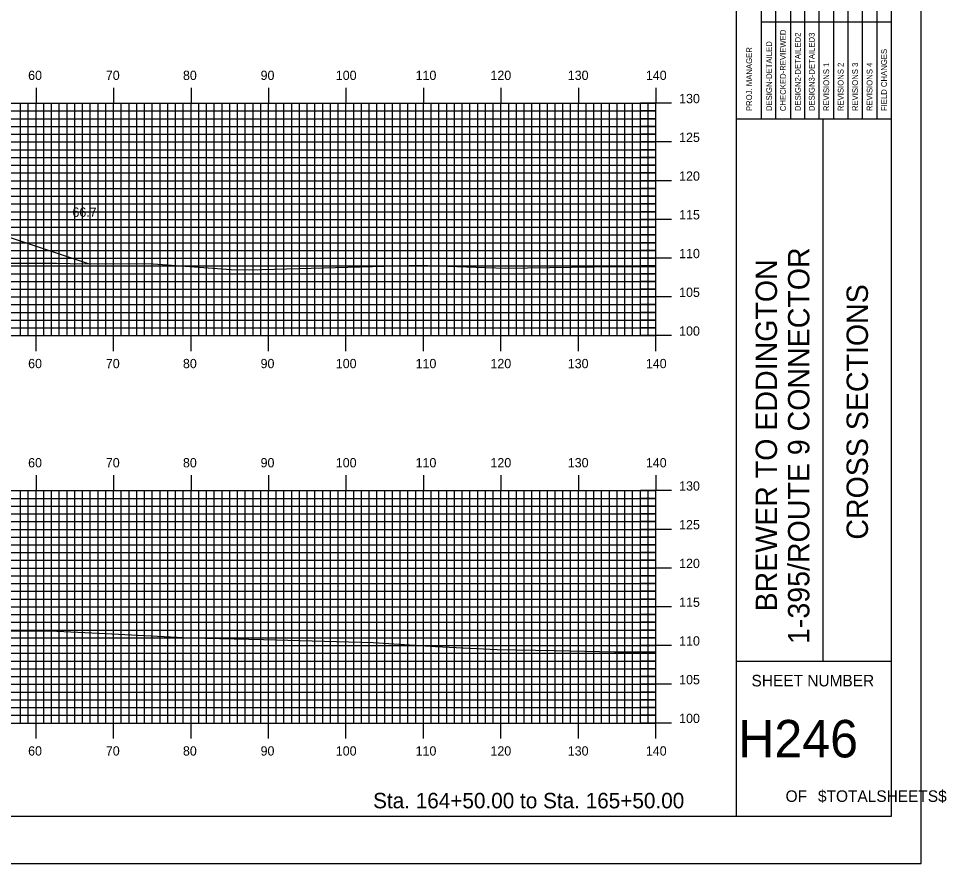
# Model space of a CAD drawing. Extents: x 1781073 to 1781416, y 442591 to 442811.
# Drawn here: x 1781296.6 to 1781416.4, y 442590.5 to 442699.6 of the extents above; entities that cross this region are included whole.
import ezdxf

# ---------------------------------------------------------------- set-up
doc = ezdxf.new("R2010")
doc.units = 0
for name, color, linetype in [('BORDER', 7, 'Continuous'), ('D_Roadway_Centerline', 7, 'Continuous'), ('D_Roadway_SlopeLines', 7, 'Continuous'), ('D_Text_Standard', 7, 'Continuous'), ('H_V ANNOTATION', 7, 'Continuous'), ('MAJOR', 7, 'Continuous'), ('MINOR', 7, 'Continuous'), ('PLOT BOUNDARY', 7, 'Continuous'), ('S_Roadway_Centerline', 7, 'Continuous')]:
    doc.layers.add(name, color=color, linetype=linetype)

msp = doc.modelspace()

# ---------------------------------------------------------------- linework, layer by layer
at = {"layer": 'BORDER'}
for p, q in [((1781389.29, 442596.67), (1781389.29, 442806.67)), ((1781389.29, 442686.67), (1781409.29, 442686.67)), ((1781400.48, 442616.67), (1781400.48, 442686.67)), ((1781389.29, 442616.67), (1781409.29, 442616.67))]:
    msp.add_line(p, q, dxfattribs=at)
msp.add_lwpolyline([(1781089.29, 442596.67), (1781409.29, 442596.67), (1781409.29, 442806.67), (1781089.29, 442806.67)], close=True, dxfattribs=at)
for points in [[(1781394.39, 442686.68), (1781394.39, 442721.67)], [(1781396.25, 442721.67), (1781396.25, 442686.68)], [(1781398.12, 442686.68), (1781398.12, 442721.67)], [(1781399.98, 442686.68), (1781399.98, 442721.67)], [(1781401.84, 442686.68), (1781401.84, 442721.67)], [(1781403.71, 442686.68), (1781403.71, 442721.67)], [(1781405.57, 442686.68), (1781405.57, 442721.67)], [(1781407.43, 442686.68), (1781407.43, 442721.67)], [(1781392.53, 442686.68), (1781392.53, 442720.26)], [(1781392.52, 442699.17), (1781409.29, 442699.17)]]:
    msp.add_lwpolyline(points, dxfattribs=at)
at = {"layer": 'D_Roadway_Centerline'}
msp.add_lwpolyline([(1781185.99, 442672.58), (1781206.89, 442679.55), (1781208.72, 442680.01), (1781218.89, 442682.55), (1781226.89, 442682.87), (1781238.89, 442683.11), (1781250.89, 442682.87), (1781258.89, 442682.55), (1781269.07, 442680.01), (1781270.89, 442679.55), (1781305.63, 442667.98)], dxfattribs=at)
at = {"layer": 'D_Roadway_SlopeLines'}
msp.add_lwpolyline([(1781258.89, 442682.55), (1781270.89, 442679.55), (1781305.63, 442667.98)], dxfattribs=at)
at = {"layer": 'MAJOR'}
for p, q in [((1781298.89, 442690.67), (1781298.89, 442688.67)), ((1781308.89, 442690.67), (1781308.89, 442688.67)), ((1781318.89, 442690.67), (1781318.89, 442688.67)), ((1781328.89, 442690.67), (1781328.89, 442688.67)), ((1781338.89, 442690.67), (1781338.89, 442688.67)), ((1781348.89, 442690.67), (1781348.89, 442688.67)), ((1781358.89, 442690.67), (1781358.89, 442688.67)), ((1781368.89, 442690.67), (1781368.89, 442688.67)), ((1781378.89, 442690.67), (1781378.89, 442688.67)), ((1781098.89, 442688.67), (1781378.89, 442688.67)), ((1781098.89, 442688.67), (1781378.89, 442688.67)), ((1781298.89, 442658.67), (1781298.89, 442688.67)), ((1781308.89, 442658.67), (1781308.89, 442688.67)), ((1781318.89, 442658.67), (1781318.89, 442688.67)), ((1781328.89, 442658.67), (1781328.89, 442688.67)), ((1781338.89, 442658.67), (1781338.89, 442688.67)), ((1781348.89, 442658.67), (1781348.89, 442688.67)), ((1781358.89, 442658.67), (1781358.89, 442688.67)), ((1781368.89, 442658.67), (1781368.89, 442688.67)), ((1781380.9, 442688.67), (1781376.89, 442688.67)), ((1781378.89, 442658.67), (1781378.89, 442688.67)), ((1781378.89, 442658.67), (1781378.89, 442688.67)), ((1781098.89, 442683.67), (1781378.89, 442683.67)), ((1781380.9, 442683.67), (1781376.89, 442683.67)), ((1781098.89, 442678.67), (1781378.89, 442678.67)), ((1781380.9, 442678.67), (1781376.89, 442678.67)), ((1781098.89, 442673.67), (1781378.89, 442673.67)), ((1781380.9, 442673.67), (1781376.89, 442673.67)), ((1781098.89, 442668.67), (1781378.89, 442668.67)), ((1781380.9, 442668.67), (1781376.89, 442668.67)), ((1781098.89, 442663.67), (1781378.89, 442663.67)), ((1781380.9, 442663.67), (1781376.89, 442663.67)), ((1781098.89, 442658.67), (1781378.89, 442658.67)), ((1781098.89, 442658.67), (1781378.89, 442658.67)), ((1781298.89, 442656.66), (1781298.89, 442658.67)), ((1781308.89, 442656.66), (1781308.89, 442658.67)), ((1781318.89, 442656.66), (1781318.89, 442658.67)), ((1781328.89, 442656.66), (1781328.89, 442658.67)), ((1781338.89, 442656.66), (1781338.89, 442658.67)), ((1781348.89, 442656.66), (1781348.89, 442658.67)), ((1781358.89, 442656.66), (1781358.89, 442658.67)), ((1781368.89, 442656.66), (1781368.89, 442658.67)), ((1781380.9, 442658.67), (1781376.89, 442658.67)), ((1781378.89, 442656.66), (1781378.89, 442658.67)), ((1781298.89, 442640.67), (1781298.89, 442638.67)), ((1781308.89, 442640.67), (1781308.89, 442638.67)), ((1781318.89, 442640.67), (1781318.89, 442638.67)), ((1781328.89, 442640.67), (1781328.89, 442638.67)), ((1781338.89, 442640.67), (1781338.89, 442638.67)), ((1781348.89, 442640.67), (1781348.89, 442638.67)), ((1781358.89, 442640.67), (1781358.89, 442638.67)), ((1781368.89, 442640.67), (1781368.89, 442638.67)), ((1781378.89, 442640.67), (1781378.89, 442638.67)), ((1781098.89, 442638.67), (1781378.89, 442638.67)), ((1781098.89, 442638.67), (1781378.89, 442638.67)), ((1781298.89, 442608.67), (1781298.89, 442638.67)), ((1781308.89, 442608.67), (1781308.89, 442638.67)), ((1781318.89, 442608.67), (1781318.89, 442638.67)), ((1781328.89, 442608.67), (1781328.89, 442638.67)), ((1781338.89, 442608.67), (1781338.89, 442638.67)), ((1781348.89, 442608.67), (1781348.89, 442638.67)), ((1781358.89, 442608.67), (1781358.89, 442638.67)), ((1781368.89, 442608.67), (1781368.89, 442638.67)), ((1781380.9, 442638.67), (1781376.89, 442638.67)), ((1781378.89, 442608.67), (1781378.89, 442638.67)), ((1781378.89, 442608.67), (1781378.89, 442638.67)), ((1781098.89, 442633.67), (1781378.89, 442633.67)), ((1781380.9, 442633.67), (1781376.89, 442633.67)), ((1781098.89, 442628.67), (1781378.89, 442628.67)), ((1781380.9, 442628.67), (1781376.89, 442628.67)), ((1781098.89, 442623.67), (1781378.89, 442623.67)), ((1781380.9, 442623.67), (1781376.89, 442623.67)), ((1781098.89, 442618.67), (1781378.89, 442618.67)), ((1781380.9, 442618.67), (1781376.89, 442618.67)), ((1781098.89, 442613.67), (1781378.89, 442613.67)), ((1781380.9, 442613.67), (1781376.89, 442613.67)), ((1781098.89, 442608.67), (1781378.89, 442608.67)), ((1781098.89, 442608.67), (1781378.89, 442608.67)), ((1781298.89, 442606.66), (1781298.89, 442608.67)), ((1781308.89, 442606.66), (1781308.89, 442608.67)), ((1781318.89, 442606.66), (1781318.89, 442608.67)), ((1781328.89, 442606.66), (1781328.89, 442608.67)), ((1781338.89, 442606.66), (1781338.89, 442608.67)), ((1781348.89, 442606.66), (1781348.89, 442608.67)), ((1781358.89, 442606.66), (1781358.89, 442608.67)), ((1781368.89, 442606.66), (1781368.89, 442608.67)), ((1781380.9, 442608.67), (1781376.89, 442608.67)), ((1781378.89, 442606.66), (1781378.89, 442608.67))]:
    msp.add_line(p, q, dxfattribs=at)
at = {"layer": 'MINOR'}
for p, q in [((1781296.89, 442658.67), (1781296.89, 442688.67)), ((1781297.89, 442658.67), (1781297.89, 442688.67)), ((1781299.89, 442658.67), (1781299.89, 442688.67)), ((1781300.89, 442658.67), (1781300.89, 442688.67)), ((1781301.89, 442658.67), (1781301.89, 442688.67)), ((1781302.89, 442658.67), (1781302.89, 442688.67)), ((1781303.89, 442658.67), (1781303.89, 442688.67)), ((1781304.89, 442658.67), (1781304.89, 442688.67)), ((1781305.89, 442658.67), (1781305.89, 442688.67)), ((1781306.89, 442658.67), (1781306.89, 442688.67)), ((1781307.89, 442658.67), (1781307.89, 442688.67)), ((1781309.89, 442658.67), (1781309.89, 442688.67)), ((1781310.89, 442658.67), (1781310.89, 442688.67)), ((1781311.89, 442658.67), (1781311.89, 442688.67)), ((1781312.89, 442658.67), (1781312.89, 442688.67)), ((1781313.89, 442658.67), (1781313.89, 442688.67)), ((1781314.89, 442658.67), (1781314.89, 442688.67)), ((1781315.89, 442658.67), (1781315.89, 442688.67)), ((1781316.89, 442658.67), (1781316.89, 442688.67)), ((1781317.89, 442658.67), (1781317.89, 442688.67)), ((1781319.89, 442658.67), (1781319.89, 442688.67)), ((1781320.89, 442658.67), (1781320.89, 442688.67)), ((1781321.89, 442658.67), (1781321.89, 442688.67)), ((1781322.89, 442658.67), (1781322.89, 442688.67)), ((1781323.89, 442658.67), (1781323.89, 442688.67)), ((1781324.89, 442658.67), (1781324.89, 442688.67)), ((1781325.89, 442658.67), (1781325.89, 442688.67)), ((1781326.89, 442658.67), (1781326.89, 442688.67)), ((1781327.89, 442658.67), (1781327.89, 442688.67)), ((1781329.89, 442658.67), (1781329.89, 442688.67)), ((1781330.89, 442658.67), (1781330.89, 442688.67)), ((1781331.89, 442658.67), (1781331.89, 442688.67)), ((1781332.89, 442658.67), (1781332.89, 442688.67)), ((1781333.89, 442658.67), (1781333.89, 442688.67)), ((1781334.89, 442658.67), (1781334.89, 442688.67)), ((1781335.89, 442658.67), (1781335.89, 442688.67)), ((1781336.89, 442658.67), (1781336.89, 442688.67)), ((1781337.89, 442658.67), (1781337.89, 442688.67)), ((1781339.89, 442658.67), (1781339.89, 442688.67)), ((1781340.89, 442658.67), (1781340.89, 442688.67)), ((1781341.89, 442658.67), (1781341.89, 442688.67)), ((1781342.89, 442658.67), (1781342.89, 442688.67)), ((1781343.89, 442658.67), (1781343.89, 442688.67)), ((1781344.89, 442658.67), (1781344.89, 442688.67)), ((1781345.89, 442658.67), (1781345.89, 442688.67)), ((1781346.89, 442658.67), (1781346.89, 442688.67)), ((1781347.89, 442658.67), (1781347.89, 442688.67)), ((1781349.89, 442658.67), (1781349.89, 442688.67)), ((1781350.89, 442658.67), (1781350.89, 442688.67)), ((1781351.89, 442658.67), (1781351.89, 442688.67)), ((1781352.89, 442658.67), (1781352.89, 442688.67)), ((1781353.89, 442658.67), (1781353.89, 442688.67)), ((1781354.89, 442658.67), (1781354.89, 442688.67)), ((1781355.89, 442658.67), (1781355.89, 442688.67)), ((1781356.89, 442658.67), (1781356.89, 442688.67)), ((1781357.89, 442658.67), (1781357.89, 442688.67)), ((1781359.89, 442658.67), (1781359.89, 442688.67)), ((1781360.89, 442658.67), (1781360.89, 442688.67)), ((1781361.89, 442658.67), (1781361.89, 442688.67)), ((1781362.89, 442658.67), (1781362.89, 442688.67)), ((1781363.89, 442658.67), (1781363.89, 442688.67)), ((1781364.89, 442658.67), (1781364.89, 442688.67)), ((1781365.89, 442658.67), (1781365.89, 442688.67)), ((1781366.89, 442658.67), (1781366.89, 442688.67)), ((1781367.89, 442658.67), (1781367.89, 442688.67)), ((1781369.89, 442658.67), (1781369.89, 442688.67)), ((1781370.89, 442658.67), (1781370.89, 442688.67)), ((1781371.89, 442658.67), (1781371.89, 442688.67)), ((1781372.89, 442658.67), (1781372.89, 442688.67)), ((1781373.89, 442658.67), (1781373.89, 442688.67)), ((1781374.89, 442658.67), (1781374.89, 442688.67)), ((1781375.89, 442658.67), (1781375.89, 442688.67)), ((1781376.89, 442658.67), (1781376.89, 442688.67)), ((1781377.89, 442658.67), (1781377.89, 442688.67)), ((1781098.89, 442687.67), (1781378.89, 442687.67)), ((1781098.89, 442686.67), (1781378.89, 442686.67)), ((1781378.89, 442687.67), (1781376.89, 442687.67)), ((1781378.89, 442686.67), (1781376.89, 442686.67)), ((1781098.89, 442685.67), (1781378.89, 442685.67)), ((1781378.89, 442685.67), (1781376.89, 442685.67)), ((1781098.89, 442684.67), (1781378.89, 442684.67)), ((1781378.89, 442684.67), (1781376.89, 442684.67)), ((1781098.89, 442682.67), (1781378.89, 442682.67)), ((1781378.89, 442682.67), (1781376.89, 442682.67)), ((1781098.89, 442681.67), (1781378.89, 442681.67)), ((1781098.89, 442680.67), (1781378.89, 442680.67)), ((1781378.89, 442681.67), (1781376.89, 442681.67)), ((1781378.89, 442680.67), (1781376.89, 442680.67)), ((1781098.89, 442679.67), (1781378.89, 442679.67)), ((1781378.89, 442679.67), (1781376.89, 442679.67)), ((1781098.89, 442677.67), (1781378.89, 442677.67)), ((1781378.89, 442677.67), (1781376.89, 442677.67)), ((1781098.89, 442676.67), (1781378.89, 442676.67)), ((1781378.89, 442676.67), (1781376.89, 442676.67)), ((1781098.89, 442675.67), (1781378.89, 442675.67)), ((1781098.89, 442674.67), (1781378.89, 442674.67)), ((1781378.89, 442675.67), (1781376.89, 442675.67)), ((1781378.89, 442674.67), (1781376.89, 442674.67)), ((1781098.89, 442672.67), (1781378.89, 442672.67)), ((1781378.89, 442672.67), (1781376.89, 442672.67)), ((1781098.89, 442671.67), (1781378.89, 442671.67)), ((1781378.89, 442671.67), (1781376.89, 442671.67)), ((1781098.89, 442670.67), (1781378.89, 442670.67)), ((1781378.89, 442670.67), (1781376.89, 442670.67)), ((1781098.89, 442669.67), (1781378.89, 442669.67)), ((1781378.89, 442669.67), (1781376.89, 442669.67)), ((1781098.89, 442667.67), (1781378.89, 442667.67)), ((1781378.89, 442667.67), (1781376.89, 442667.67)), ((1781098.89, 442666.67), (1781378.89, 442666.67)), ((1781378.89, 442666.67), (1781376.89, 442666.67)), ((1781098.89, 442665.67), (1781378.89, 442665.67)), ((1781378.89, 442665.67), (1781376.89, 442665.67)), ((1781098.89, 442664.67), (1781378.89, 442664.67)), ((1781378.89, 442664.67), (1781376.89, 442664.67)), ((1781098.89, 442662.67), (1781378.89, 442662.67)), ((1781378.89, 442662.67), (1781376.89, 442662.67)), ((1781098.89, 442661.67), (1781378.89, 442661.67)), ((1781378.89, 442661.67), (1781376.89, 442661.67)), ((1781098.89, 442660.67), (1781378.89, 442660.67)), ((1781378.89, 442660.67), (1781376.89, 442660.67)), ((1781098.89, 442659.67), (1781378.89, 442659.67)), ((1781378.89, 442659.67), (1781376.89, 442659.67)), ((1781296.89, 442608.67), (1781296.89, 442638.67)), ((1781297.89, 442608.67), (1781297.89, 442638.67)), ((1781299.89, 442608.67), (1781299.89, 442638.67)), ((1781300.89, 442608.67), (1781300.89, 442638.67)), ((1781301.89, 442608.67), (1781301.89, 442638.67)), ((1781302.89, 442608.67), (1781302.89, 442638.67)), ((1781303.89, 442608.67), (1781303.89, 442638.67)), ((1781304.89, 442608.67), (1781304.89, 442638.67)), ((1781305.89, 442608.67), (1781305.89, 442638.67)), ((1781306.89, 442608.67), (1781306.89, 442638.67)), ((1781307.89, 442608.67), (1781307.89, 442638.67)), ((1781309.89, 442608.67), (1781309.89, 442638.67)), ((1781310.89, 442608.67), (1781310.89, 442638.67)), ((1781311.89, 442608.67), (1781311.89, 442638.67)), ((1781312.89, 442608.67), (1781312.89, 442638.67)), ((1781313.89, 442608.67), (1781313.89, 442638.67)), ((1781314.89, 442608.67), (1781314.89, 442638.67)), ((1781315.89, 442608.67), (1781315.89, 442638.67)), ((1781316.89, 442608.67), (1781316.89, 442638.67)), ((1781317.89, 442608.67), (1781317.89, 442638.67)), ((1781319.89, 442608.67), (1781319.89, 442638.67)), ((1781320.89, 442608.67), (1781320.89, 442638.67)), ((1781321.89, 442608.67), (1781321.89, 442638.67)), ((1781322.89, 442608.67), (1781322.89, 442638.67)), ((1781323.89, 442608.67), (1781323.89, 442638.67)), ((1781324.89, 442608.67), (1781324.89, 442638.67)), ((1781325.89, 442608.67), (1781325.89, 442638.67)), ((1781326.89, 442608.67), (1781326.89, 442638.67)), ((1781327.89, 442608.67), (1781327.89, 442638.67)), ((1781329.89, 442608.67), (1781329.89, 442638.67)), ((1781330.89, 442608.67), (1781330.89, 442638.67)), ((1781331.89, 442608.67), (1781331.89, 442638.67)), ((1781332.89, 442608.67), (1781332.89, 442638.67)), ((1781333.89, 442608.67), (1781333.89, 442638.67)), ((1781334.89, 442608.67), (1781334.89, 442638.67)), ((1781335.89, 442608.67), (1781335.89, 442638.67)), ((1781336.89, 442608.67), (1781336.89, 442638.67)), ((1781337.89, 442608.67), (1781337.89, 442638.67)), ((1781339.89, 442608.67), (1781339.89, 442638.67)), ((1781340.89, 442608.67), (1781340.89, 442638.67)), ((1781341.89, 442608.67), (1781341.89, 442638.67)), ((1781342.89, 442608.67), (1781342.89, 442638.67)), ((1781343.89, 442608.67), (1781343.89, 442638.67)), ((1781344.89, 442608.67), (1781344.89, 442638.67)), ((1781345.89, 442608.67), (1781345.89, 442638.67)), ((1781346.89, 442608.67), (1781346.89, 442638.67)), ((1781347.89, 442608.67), (1781347.89, 442638.67)), ((1781349.89, 442608.67), (1781349.89, 442638.67)), ((1781350.89, 442608.67), (1781350.89, 442638.67)), ((1781351.89, 442608.67), (1781351.89, 442638.67)), ((1781352.89, 442608.67), (1781352.89, 442638.67)), ((1781353.89, 442608.67), (1781353.89, 442638.67)), ((1781354.89, 442608.67), (1781354.89, 442638.67)), ((1781355.89, 442608.67), (1781355.89, 442638.67)), ((1781356.89, 442608.67), (1781356.89, 442638.67)), ((1781357.89, 442608.67), (1781357.89, 442638.67)), ((1781359.89, 442608.67), (1781359.89, 442638.67)), ((1781360.89, 442608.67), (1781360.89, 442638.67)), ((1781361.89, 442608.67), (1781361.89, 442638.67)), ((1781362.89, 442608.67), (1781362.89, 442638.67)), ((1781363.89, 442608.67), (1781363.89, 442638.67)), ((1781364.89, 442608.67), (1781364.89, 442638.67)), ((1781365.89, 442608.67), (1781365.89, 442638.67)), ((1781366.89, 442608.67), (1781366.89, 442638.67)), ((1781367.89, 442608.67), (1781367.89, 442638.67)), ((1781369.89, 442608.67), (1781369.89, 442638.67)), ((1781370.89, 442608.67), (1781370.89, 442638.67)), ((1781371.89, 442608.67), (1781371.89, 442638.67)), ((1781372.89, 442608.67), (1781372.89, 442638.67)), ((1781373.89, 442608.67), (1781373.89, 442638.67)), ((1781374.89, 442608.67), (1781374.89, 442638.67)), ((1781375.89, 442608.67), (1781375.89, 442638.67)), ((1781376.89, 442608.67), (1781376.89, 442638.67)), ((1781377.89, 442608.67), (1781377.89, 442638.67)), ((1781098.89, 442637.67), (1781378.89, 442637.67)), ((1781378.89, 442637.67), (1781376.89, 442637.67)), ((1781098.89, 442636.67), (1781378.89, 442636.67)), ((1781378.89, 442636.67), (1781376.89, 442636.67)), ((1781098.89, 442635.67), (1781378.89, 442635.67)), ((1781378.89, 442635.67), (1781376.89, 442635.67)), ((1781098.89, 442634.67), (1781378.89, 442634.67)), ((1781378.89, 442634.67), (1781376.89, 442634.67)), ((1781098.89, 442632.67), (1781378.89, 442632.67)), ((1781378.89, 442632.67), (1781376.89, 442632.67)), ((1781098.89, 442631.67), (1781378.89, 442631.67)), ((1781378.89, 442631.67), (1781376.89, 442631.67)), ((1781098.89, 442630.67), (1781378.89, 442630.67)), ((1781378.89, 442630.67), (1781376.89, 442630.67)), ((1781098.89, 442629.67), (1781378.89, 442629.67)), ((1781378.89, 442629.67), (1781376.89, 442629.67)), ((1781098.89, 442627.67), (1781378.89, 442627.67)), ((1781098.89, 442626.67), (1781378.89, 442626.67)), ((1781378.89, 442627.67), (1781376.89, 442627.67)), ((1781378.89, 442626.67), (1781376.89, 442626.67)), ((1781098.89, 442625.67), (1781378.89, 442625.67)), ((1781378.89, 442625.67), (1781376.89, 442625.67)), ((1781098.89, 442624.67), (1781378.89, 442624.67)), ((1781378.89, 442624.67), (1781376.89, 442624.67)), ((1781098.89, 442622.67), (1781378.89, 442622.67)), ((1781378.89, 442622.67), (1781376.89, 442622.67)), ((1781098.89, 442621.67), (1781378.89, 442621.67)), ((1781098.89, 442620.67), (1781378.89, 442620.67)), ((1781378.89, 442621.67), (1781376.89, 442621.67)), ((1781378.89, 442620.67), (1781376.89, 442620.67)), ((1781098.89, 442619.67), (1781378.89, 442619.67)), ((1781378.89, 442619.67), (1781376.89, 442619.67)), ((1781098.89, 442617.67), (1781378.89, 442617.67)), ((1781378.89, 442617.67), (1781376.89, 442617.67)), ((1781098.89, 442616.67), (1781378.89, 442616.67)), ((1781378.89, 442616.67), (1781376.89, 442616.67)), ((1781098.89, 442615.67), (1781378.89, 442615.67)), ((1781098.89, 442614.67), (1781378.89, 442614.67)), ((1781378.89, 442615.67), (1781376.89, 442615.67)), ((1781378.89, 442614.67), (1781376.89, 442614.67)), ((1781098.89, 442612.67), (1781378.89, 442612.67)), ((1781378.89, 442612.67), (1781376.89, 442612.67)), ((1781098.89, 442611.67), (1781378.89, 442611.67)), ((1781378.89, 442611.67), (1781376.89, 442611.67)), ((1781098.89, 442610.67), (1781378.89, 442610.67)), ((1781378.89, 442610.67), (1781376.89, 442610.67)), ((1781098.89, 442609.67), (1781378.89, 442609.67)), ((1781378.89, 442609.67), (1781376.89, 442609.67))]:
    msp.add_line(p, q, dxfattribs=at)
at = {"layer": 'PLOT BOUNDARY'}
msp.add_lwpolyline([(1781073.11, 442590.55), (1781413.11, 442590.55), (1781413.11, 442810.55), (1781073.11, 442810.55)], close=True, dxfattribs=at)
at = {"layer": 'S_Roadway_Centerline'}
for points in [[(1781289.95, 442668.04), (1781299.54, 442668.01), (1781301.53, 442668.04), (1781303.28, 442667.99), (1781314.01, 442667.92), (1781324.09, 442667.21), (1781326.43, 442667.16), (1781347.09, 442667.72), (1781349.4, 442667.71), (1781359.48, 442667.38), (1781370.84, 442667.57), (1781372.8, 442667.59), (1781378.89, 442667.6)], [(1781294.69, 442620.58), (1781301.58, 442620.54), (1781306.99, 442620.29), (1781318.77, 442619.65), (1781328.23, 442619.44), (1781342.38, 442619.06), (1781350.43, 442618.55), (1781358.42, 442618.14), (1781365.86, 442618.04), (1781373.56, 442617.88), (1781378.89, 442617.86)]]:
    msp.add_lwpolyline(points, dxfattribs=at)

# ---------------------------------------------------------------- texts
at = {"layer": 'BORDER'}
for s, height, p in [('CHECKED-REVIEWED', 0.7455, (1781395.66, 442687.65)), ('DESIGN2-DETAILED2', 0.7455, (1781397.59, 442687.65)), ('DESIGN3-DETAILED3', 0.7455, (1781399.38, 442687.65)), ('DESIGN-DETAILED', 0.7455, (1781393.87, 442687.65)), ('PROJ. MANAGER', 0.7455, (1781391.3, 442687.65)), ('FIELD CHANGES', 0.7455, (1781408.7, 442687.65)), ('REVISIONS 1', 0.7455, (1781401.25, 442687.65)), ('REVISIONS 2', 0.7455, (1781403.11, 442687.65)), ('REVISIONS 3', 0.7455, (1781404.97, 442687.65)), ('REVISIONS 4', 0.7455, (1781406.84, 442687.65)), ('1-395/ROUTE 9 CONNECTOR', 2.7557, (1781398.7, 442618.87)), ('BREWER TO EDDINGTON', 2.7557, (1781394.52, 442623.07)), ('CROSS SECTIONS', 2.7557, (1781406.26, 442632.34))]:
    msp.add_text(s, height=height, rotation=90, dxfattribs=at).set_placement(p)
for s, height, p in [('SHEET NUMBER', 1.4905, (1781391.23, 442613.4)), ('H246', 4.839, (1781389.51, 442604.23)), ('OF', 1.491, (1781395.63, 442598.49)), ('$TOTALSHEETS$', 1.4905, (1781399.81, 442598.49))]:
    msp.add_text(s, height=height, dxfattribs=at).set_placement(p)
at = {"layer": 'D_Text_Standard'}
msp.add_text("66.7'", height=1.2, dxfattribs=at).set_placement((1781303.59, 442674.01))
at = {"layer": 'H_V ANNOTATION'}
for s, height, p in [('60', 1.2, (1781297.87, 442691.67)), ('70', 1.2, (1781307.9, 442691.67)), ('80', 1.2, (1781317.85, 442691.67)), ('90', 1.2, (1781327.87, 442691.67)), ('100', 1.2, (1781337.58, 442691.67)), ('110', 1.2, (1781347.88, 442691.67)), ('120', 1.2, (1781357.54, 442691.67)), ('130', 1.2, (1781367.52, 442691.67)), ('140', 1.2, (1781377.6, 442691.67)), ('130', 1.2, (1781381.89, 442688.67)), ('125', 1.2, (1781381.89, 442683.67)), ('120', 1.2, (1781381.89, 442678.67)), ('115', 1.2, (1781381.89, 442673.67)), ('110', 1.2, (1781381.89, 442668.67)), ('105', 1.2, (1781381.89, 442663.67)), ('100', 1.2, (1781381.89, 442658.67)), ('60', 1.2, (1781297.87, 442654.47)), ('70', 1.2, (1781307.9, 442654.47)), ('80', 1.2, (1781317.85, 442654.47)), ('90', 1.2, (1781327.87, 442654.47)), ('100', 1.2, (1781337.58, 442654.47)), ('110', 1.2, (1781347.88, 442654.47)), ('120', 1.2, (1781357.54, 442654.47)), ('130', 1.2, (1781367.52, 442654.47)), ('140', 1.2, (1781377.6, 442654.47)), ('60', 1.2, (1781297.87, 442641.67)), ('70', 1.2, (1781307.9, 442641.67)), ('80', 1.2, (1781317.85, 442641.67)), ('90', 1.2, (1781327.87, 442641.67)), ('100', 1.2, (1781337.58, 442641.67)), ('110', 1.2, (1781347.88, 442641.67)), ('120', 1.2, (1781357.54, 442641.67)), ('130', 1.2, (1781367.52, 442641.67)), ('140', 1.2, (1781377.6, 442641.67)), ('130', 1.2, (1781381.89, 442638.67)), ('125', 1.2, (1781381.89, 442633.67)), ('120', 1.2, (1781381.89, 442628.67)), ('115', 1.2, (1781381.89, 442623.67)), ('110', 1.2, (1781381.89, 442618.67)), ('105', 1.2, (1781381.89, 442613.67)), ('100', 1.2, (1781381.89, 442608.67)), ('60', 1.2, (1781297.87, 442604.47)), ('70', 1.2, (1781307.9, 442604.47)), ('80', 1.2, (1781317.85, 442604.47)), ('90', 1.2, (1781327.87, 442604.47)), ('100', 1.2, (1781337.58, 442604.47)), ('110', 1.2, (1781347.88, 442604.47)), ('120', 1.2, (1781357.54, 442604.47)), ('130', 1.2, (1781367.52, 442604.47)), ('140', 1.2, (1781377.6, 442604.47)), ('Sta. 164+50.00 to Sta. 165+50.00', 2.0004, (1781342.39, 442597.66))]:
    msp.add_text(s, height=height, dxfattribs=at).set_placement(p)

doc.saveas('drawing.dxf')
